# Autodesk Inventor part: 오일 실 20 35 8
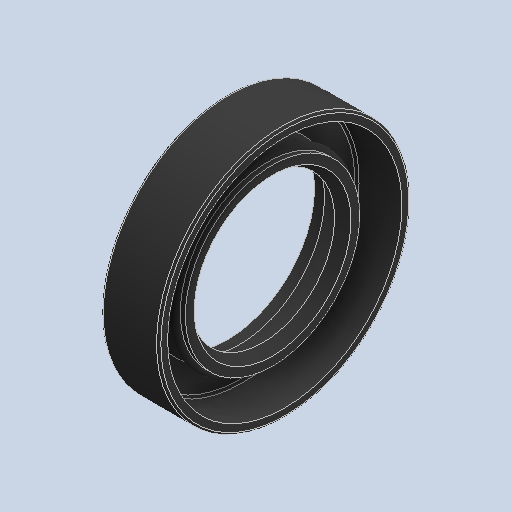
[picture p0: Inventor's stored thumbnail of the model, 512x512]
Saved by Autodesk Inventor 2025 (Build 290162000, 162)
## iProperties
Created: 2026-03
Part Number: 오일 실 20 35 8
Material: 고무
Description: 오일-실
Document SubType Name: Modeling
Designer: KDI
Density: 0.93 g/cm^3
Appearance: 기본값
Author: jhkim
Sending System: Autodesk Inventor 2026
Preprocessor: ST-DEVELOPER v20.1
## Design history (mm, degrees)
feature "Solid1"
node "솔리드1"
